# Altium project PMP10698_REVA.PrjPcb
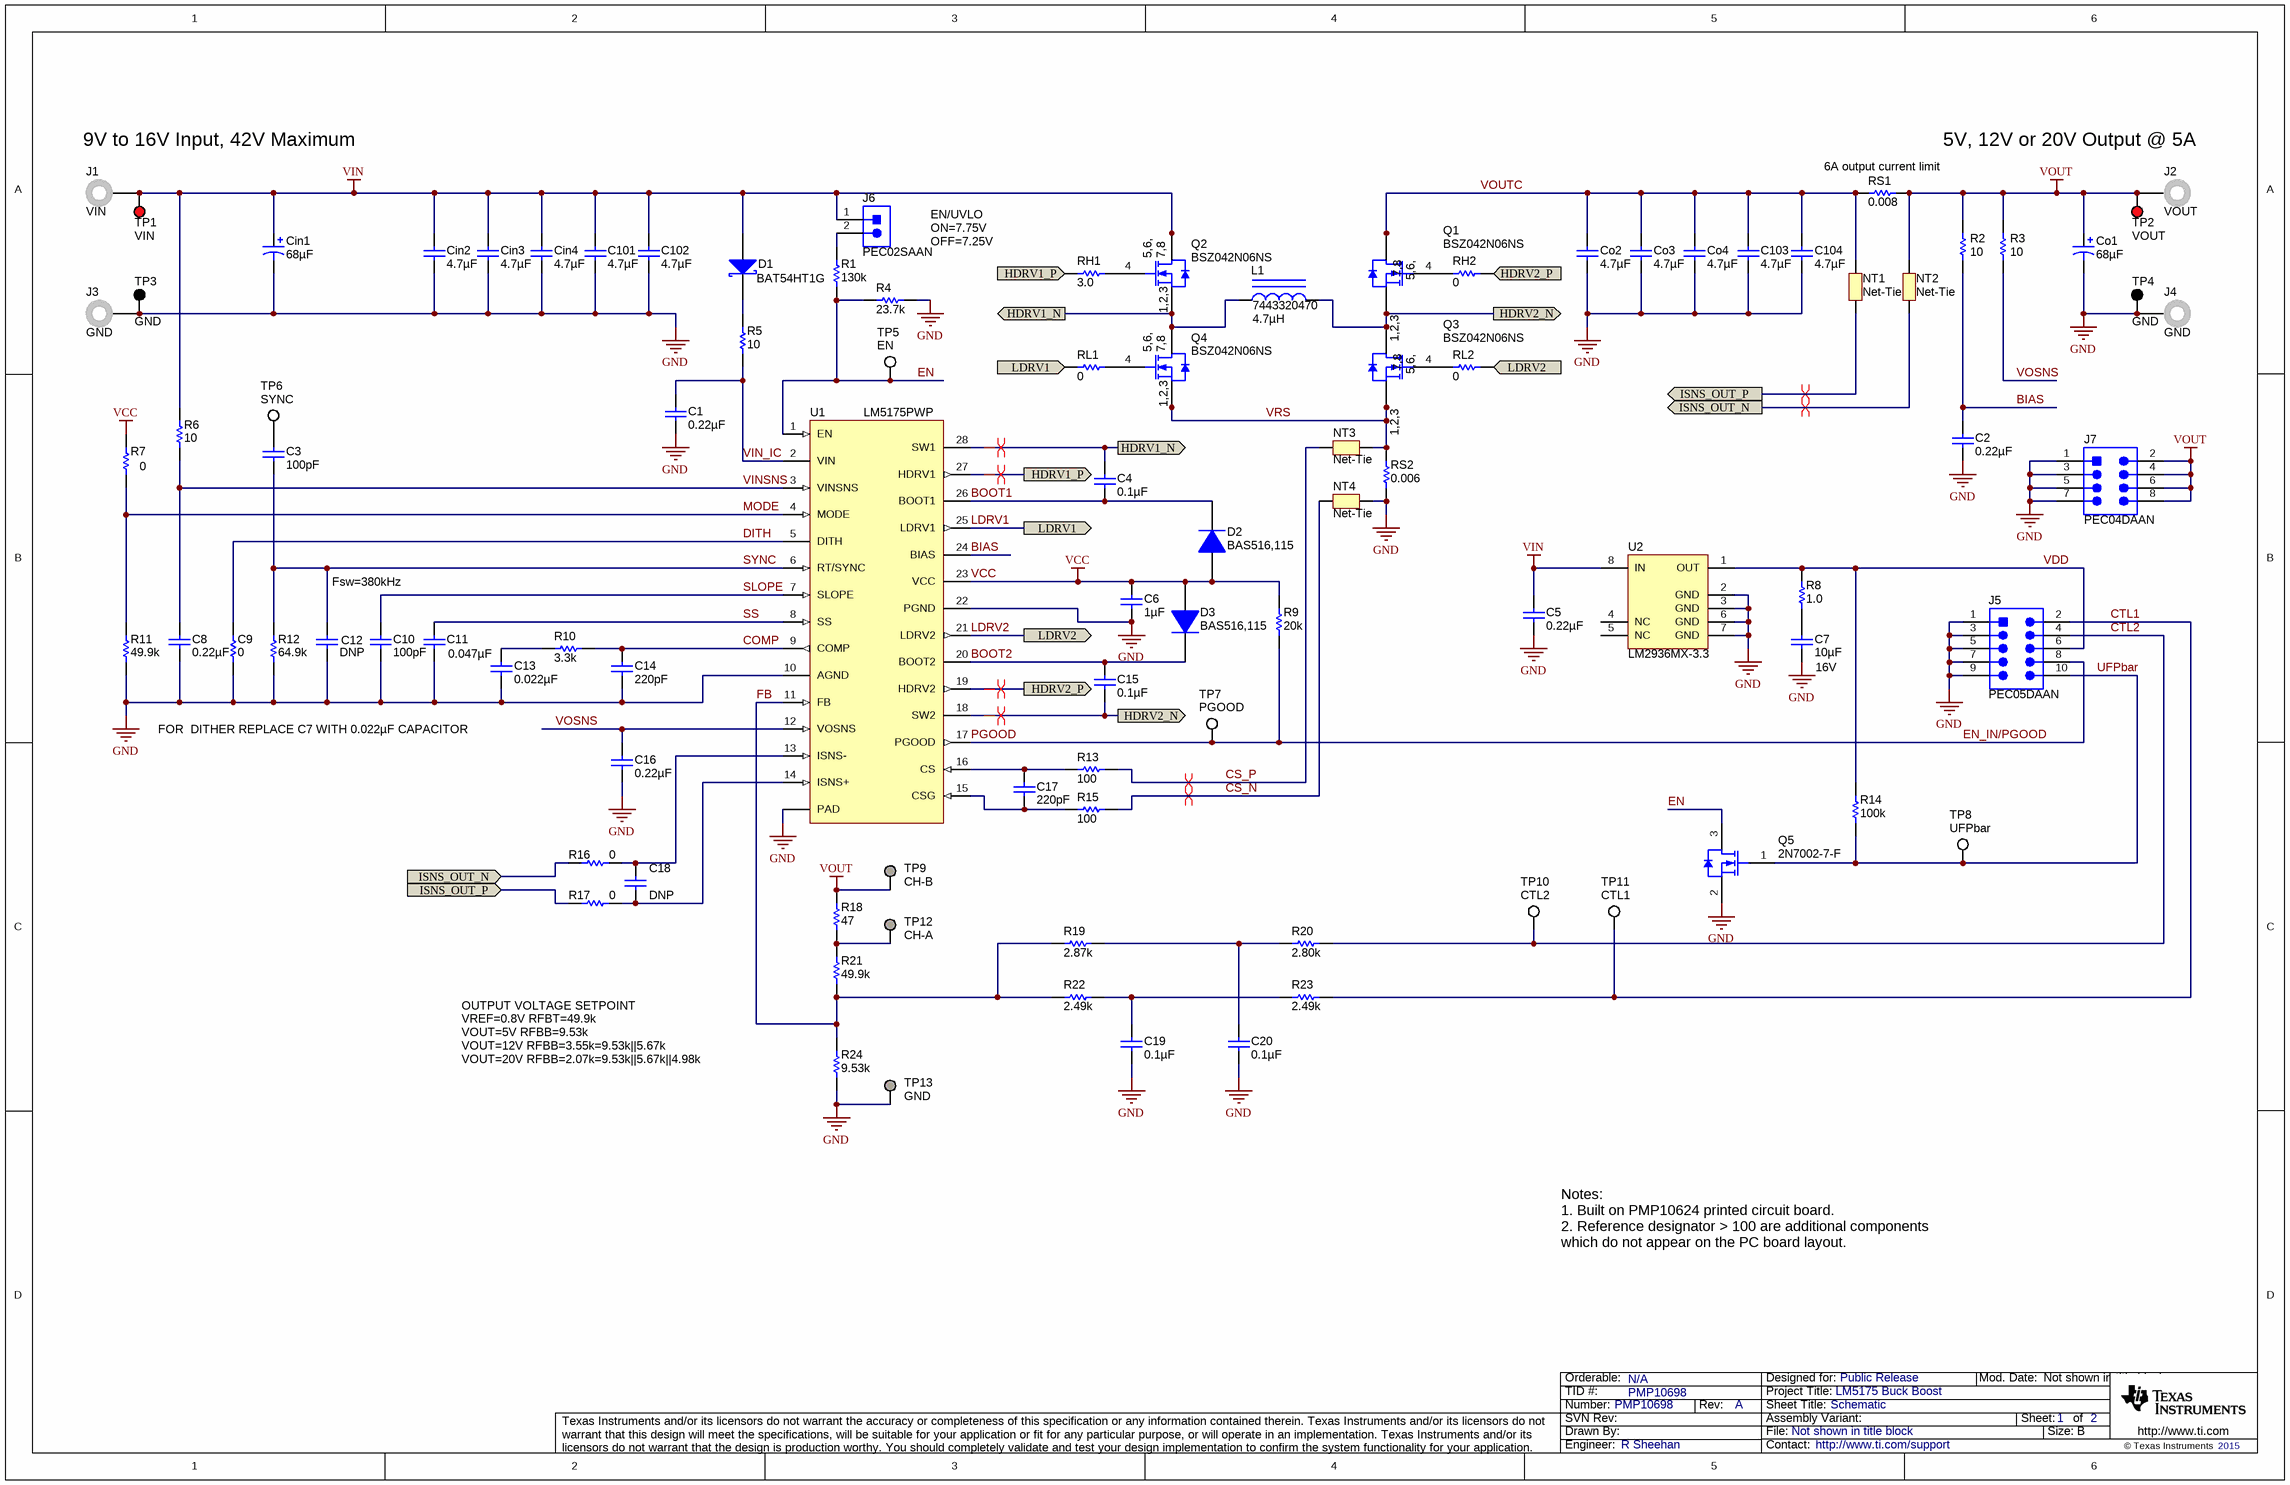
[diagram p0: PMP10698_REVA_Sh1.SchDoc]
CopyrightYear: 2015; EVM_Orderable: N/A; PCB_Rev: A; PRJ_Customer: Public Release; PRJ_Engineer: R Sheehan; PRJ_Number: PMP10698; PRJ_Title: LM5175 Buck Boost; SCH_Rev: A; TechSupport: http://www.ti.com/support; TID: PMP10698
2 sheets, 113 parts. Net scope: flat (ports and power ports of the same name join across sheets).
Board file: PMP10624_REVA.PcbDoc
Sheets:
  PMP10698_REVA_Sh1.SchDoc
  PMP10698_REVA_Sh2.SchDoc

## Sheet PMP10698_REVA_Sh1.SchDoc: Schematic
size 431 x 279 mm; Date: Not shown in title block; ApprovedBy: Not shown in title block; CheckedBy: Not shown in title block; Author: Not shown in title block; CompanyName: Not shown in title block; Engineer: Not shown in title block; Organization: Not shown in title block; Address1: Not shown in title block; Address2: Not shown in title block; Address3: Not shown in title block; Address4: Not shown in title block; DocumentNumber: 1; Revision: Use project parameter SCH_Rev; SheetNumber: 1; SheetTotal: 2; PageSetup: Record=PageOptions¦CenterHorizontal=True¦CenterVertical=True¦PrintScale=1.00¦XCorrection=1.00¦YCorrection=1.00¦PrintKind=0¦BorderSize=5000000¦LeftOffset=0¦BottomOffset=0¦Orientation=2¦PaperLength=1000¦PaperWidth=1000¦Scale=100¦PaperSource=15¦PrintQuality=600¦MediaType=1¦DitherType=10¦PaperKind=Letter¦PrintScaleMode=1

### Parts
C1  ValueDisplayed: 0.22µF  [0603L]  (hidden comment: C1608X7R1H224K080AB)
C2  ValueDisplayed: 0.22µF  [0603L]  (hidden comment: C1608X7R1H224K080AB)
C3  ValueDisplayed: 100pF  [0603L]  (hidden comment: GRM1885C1H101JA01D)
C4  ValueDisplayed: 0.1µF  [0603L]  (hidden comment: 06033C104JAT2A)
C5  ValueDisplayed: 0.22µF  [0603L]  (hidden comment: C1608X7R1H224K080AB)
C6  ValueDisplayed: 1µF  [0603L]  (hidden comment: GRM188R71C105KA12D)
C7  ValueDisplayed: 10µF  Value2: 16V  [0805_145]  (hidden comment: EMK212BB7106MG-T)
C8  ValueDisplayed: 0.22µF  [0603L]  (hidden comment: C1608X7R1H224K080AB)
C9  ValueDisplayed: 0  [0603L]  (hidden comment: CRCW06030000Z0EA)
C10  ValueDisplayed: 100pF  [0603L]  (hidden comment: GRM1885C1H101JA01D)
C11  ValueDisplayed: 0.047µF  [0603L]  (hidden comment: GRM188R71H473KA61D)
C12  DNP  [0603L]
C13  ValueDisplayed: 0.022µF  [0603L]  (hidden comment: GRM188R71H223KA01D)
C14  ValueDisplayed: 220pF  [0603L]  (hidden comment: GRM1885C1H221JA01D)
C15  ValueDisplayed: 0.1µF  [0603L]  (hidden comment: 06033C104JAT2A)
C16  ValueDisplayed: 0.22µF  [0603L]  (hidden comment: C1608X7R1H224K080AB)
C17  ValueDisplayed: 220pF  [0603L]  (hidden comment: GRM1885C1H221JA01D)
C18  DNP  [0603L]
C19  ValueDisplayed: 0.1µF  [0603L]  (hidden comment: 06033C104JAT2A)
C20  ValueDisplayed: 0.1µF  [0603L]  (hidden comment: 06033C104JAT2A)
C101  ValueDisplayed: 4.7µF  [1206L]  (hidden comment: GRM31CR71H475KA12L)
C102  ValueDisplayed: 4.7µF  [1206L]  (hidden comment: GRM31CR71H475KA12L)
C103  ValueDisplayed: 4.7µF  [1206L]  (hidden comment: GRM31CR71H475KA12L)
C104  ValueDisplayed: 4.7µF  [1206L]  (hidden comment: GRM31CR71H475KA12L)
Cin1  ValueDisplayed: 68µF  [SM_RADIAL_F]  (hidden comment: EEE-FK1J680UP)
Cin2  ValueDisplayed: 4.7µF  [1206L]  (hidden comment: GRM31CR71H475KA12L)
Cin3  ValueDisplayed: 4.7µF  [1206L]  (hidden comment: GRM31CR71H475KA12L)
Cin4  ValueDisplayed: 4.7µF  [1206L]  (hidden comment: GRM31CR71H475KA12L)
Co1  ValueDisplayed: 68µF  [SM_RADIAL_F]  (hidden comment: EEE-FK1J680UP)
Co2  ValueDisplayed: 4.7µF  [1206L]  (hidden comment: GRM31CR71H475KA12L)
Co3  ValueDisplayed: 4.7µF  [1206L]  (hidden comment: GRM31CR71H475KA12L)
Co4  ValueDisplayed: 4.7µF  [1206L]  (hidden comment: GRM31CR71H475KA12L)
D1  BAT54HT1G  [sod-323]
D2  BAS516,115  [SOD-523]
D3  BAS516,115  [SOD-523]
J1  VIN  [Keystone_575-4]
J2  VOUT  [Keystone_575-4]
J3  GND  [Keystone_575-4]
J4  GND  [Keystone_575-4]
J5  PEC05DAAN  [CONN_PEC05DAAN]
J6  PEC02SAAN  [CONN_PEC02SAAN]
J7  PEC04DAAN  [CONN_PEC04DAAN]
L1  7443320470  ValueDisplayed: 4.7µH  [WE-HCC_1210]
NT1  Net-Tie  [Net-Tie_10mil]  (net tie, no BOM)
NT2  Net-Tie  [Net-Tie_10mil]  (net tie, no BOM)
NT3  Net-Tie  [Net-Tie_10mil]  (net tie, no BOM)
NT4  Net-Tie  [Net-Tie_10mil]  (net tie, no BOM)
Q1  BSZ042N06NS  [PG-TSDSON-8]
Q2  BSZ042N06NS  [PG-TSDSON-8]
Q3  BSZ042N06NS  [PG-TSDSON-8]
Q4  BSZ042N06NS  [PG-TSDSON-8]
Q5  2N7002-7-F  [SOT-23]
R1  ValueDisplayed: 130k  [0603L]  (hidden comment: CRCW0603130KJNEA)
R2  value 10  [0603L]  (hidden comment: CRCW060310R0JNEA)
R3  ValueDisplayed: 10  [0603L]  (hidden comment: CRCW060310R0JNEA)
R4  ValueDisplayed: 23.7k  [0603L]  (hidden comment: CRCW060323K7FKEA)
R5  ValueDisplayed: 10  [0603L]  (hidden comment: CRCW060310R0JNEA)
R6  ValueDisplayed: 10  [0603L]  (hidden comment: CRCW060310R0JNEA)
R7  value 0  [0603L]  (hidden comment: CRCW06030000Z0EA)
R8  ValueDisplayed: 1.0  [0603L]  (hidden comment: CRCW06031R00JNEA)
R9  ValueDisplayed: 20k  [0603L]  (hidden comment: CRCW060320K0JNEA)
R10  ValueDisplayed: 3.3k  [0603L]  (hidden comment: CRCW06033K30JNEA)
R11  ValueDisplayed: 49.9k  [0603L]  (hidden comment: CRCW060349K9FKEA)
R12  ValueDisplayed: 64.9k  [0603L]  (hidden comment: CRCW060364K9FKEA)
R13  ValueDisplayed: 100  [0603L]  (hidden comment: CRCW0603100RFKEA)
R14  ValueDisplayed: 100k  [0603L]  (hidden comment: CRCW0603100KJNEA)
R15  ValueDisplayed: 100  [0603L]  (hidden comment: CRCW0603100RFKEA)
R16  value 0  [0603L]  (hidden comment: CRCW06030000Z0EA)
R17  value 0  [0603L]  (hidden comment: CRCW06030000Z0EA)
R18  ValueDisplayed: 47  [0603L]  (hidden comment: CRCW060347R0JNEA)
R19  ValueDisplayed: 2.87k  [0603L]  (hidden comment: CRCW06032K87FKEA)
R20  ValueDisplayed: 2.80k  [0603L]  (hidden comment: CRCW06032K80FKEA)
R21  ValueDisplayed: 49.9k  [0603L]  (hidden comment: CRCW060349K9FKEA)
R22  ValueDisplayed: 2.49k  [0603L]  (hidden comment: CRCW06032K49FKEA)
R23  ValueDisplayed: 2.49k  [0603L]  (hidden comment: CRCW06032K49FKEA)
R24  ValueDisplayed: 9.53k  [0603L]  (hidden comment: CRCW06039K53FKEA)
RH1  ValueDisplayed: 3.0  [0603L]  (hidden comment: CRCW06033R00JNEA)
RH2  value 0  [0603L]  (hidden comment: CRCW06030000Z0EA)
RL1  value 0  [0603L]  (hidden comment: CRCW06030000Z0EA)
RL2  value 0  [0603L]  (hidden comment: CRCW06030000Z0EA)
RS1  ValueDisplayed: 0.008  [2010]  (hidden comment: PMR50HZPFU8L00)
RS2  ValueDisplayed: 0.006  [2512]  (hidden comment: ERJ-M1WSF6M0U)
TP1  VIN  [Keystone5000]
TP2  VOUT  [Keystone5000]
TP3  GND  [Keystone5001]
TP4  GND  [Keystone5001]
TP5  EN  [Keystone5002]
TP6  SYNC  [Keystone5002]
TP7  PGOOD  [Keystone5002]
TP8  UFPbar  [Keystone5002]
TP9  CH-B  [Keystone1598-2]
TP10  CTL2  [Keystone5002]
TP11  CTL1  [Keystone5002]
TP12  CH-A  [Keystone1598-2]
TP13  GND  [Keystone1598-2]
U1  LM5175PWP  [PWP0028F_N]
U2  LM2936MX-3.3  [M08A_N]

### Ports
HDRV1_N, HDRV1_P (out), HDRV2_N, HDRV2_P (out), ISNS_OUT_N (in), ISNS_OUT_N (out), ISNS_OUT_P (in), ISNS_OUT_P (out), LDRV1 (out), LDRV2 (out)

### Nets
GND: C1.2 C2.2 C5.2 C6.2 C7.2 C8.1 C9.1 C10.2 C11.2 C12.1 C13.2 C14.2 C16.2 C19.2 C20.2 C101.2 C102.2 C103.2 C104.2 Cin1.2(-) Cin2.2 Cin3.2 Cin4.2 Co1.2(-) Co2.2 Co3.2 Co4.2 J3.1 J4.1 J5.1 J5.3 J5.5 J5.7 J5.9 J7.1 J7.3 J7.5 J7.7 NT4.1 Q5.2(S) R4.1 R11.1 R12.1 R24.1 RS2.1 TP3.1 TP4.1 TP13.1 U1.10(AGND) U1.22(PGND) U1.29(PAD) U2.2(GND) U2.3(GND) U2.6(GND) U2.7(GND)
VCC: C6.1 D2.2(A) D3.2(A) R7.2 R9.2 U1.23(VCC)
VIN: C5.1 C101.1 C102.1 Cin1.1(+) Cin2.1 Cin3.1 Cin4.1 D1.2(A) J1.1 J6.1 Q2.5(D) Q2.6(D) Q2.7(D) Q2.8(D) Q2.9(D) R6.1 TP1.1 U2.8(IN)
VOUT: Co1.1(+) J2.1 J7.2 J7.4 J7.6 J7.8 NT2.2 R2.2 R3.2 R18.1 RS1.2 TP2.1 TP9.1
BIAS: C2.1 R2.1 U1.24(BIAS)
BOOT1: C4.1 D2.1(K) U1.26(BOOT1)
BOOT2: C15.2 D3.1(K) U1.20(BOOT2)
COMP: C14.1 R10.2 U1.9(COMP)
CS_N: NT4.2 R15.2
CS_P: NT3.2 R13.2
CTL1: J5.2 R23.1 TP11.1
CTL2: J5.4 R20.1 TP10.1
DITH: C9.2 U1.5(DITH)
EN: Q5.3(D) R1.1 R4.2 TP5.1 U1.1(EN)
EN_IN/PGOOD: J5.8 R9.1 TP7.1 U1.17(PGOOD)  [also labelled PGOOD]
FB: R19.2 R21.1 R22.2 R24.2 U1.11(FB)
HDRV1_N: C4.2 L1.1 Q2.1(S) Q2.2(S) Q2.3(S) Q4.5(D) Q4.6(D) Q4.7(D) Q4.8(D) Q4.9(D) U1.28(SW1) ; port HDRV1_N
HDRV1_P: RH1.1 U1.27(HDRV1) ; port HDRV1_P
HDRV2_N: C15.1 L1.2 Q1.1(S) Q1.2(S) Q1.3(S) Q3.5(D) Q3.6(D) Q3.7(D) Q3.8(D) Q3.9(D) U1.18(SW2) ; port HDRV2_N
HDRV2_P: RH2.2 U1.19(HDRV2) ; port HDRV2_P
ISNS_OUT_N: NT2.1 R16.1 ; port ISNS_OUT_N
ISNS_OUT_P: NT1.1 R17.1 ; port ISNS_OUT_P
LDRV1: RL1.1 U1.25(LDRV1) ; port LDRV1
LDRV2: RL2.2 U1.21(LDRV2) ; port LDRV2
MODE: R7.1 R11.2 U1.4(MODE)
SLOPE: C10.1 U1.7(SLOPE)
SS: C11.1 U1.8(SS)
SYNC: C3.2 C12.2 R12.2 U1.6(RT/SYNC)
UFPbar: J5.10 Q5.1(G) R14.1 TP8.1
VDD: J5.6 R8.2 R14.2 U2.1(OUT)
VIN_IC: C1.1 R5.1 U1.2(VIN)
VINSNS: C8.2 R6.2 U1.3(VINSNS)
VOSNS: C16.1 R3.1 U1.12(VOSNS)
VOUTC: C103.1 C104.1 Co2.1 Co3.1 Co4.1 NT1.2 Q1.5(D) Q1.6(D) Q1.7(D) Q1.8(D) Q1.9(D) RS1.1
VRS: NT3.1 Q3.1(S) Q3.2(S) Q3.3(S) Q4.1(S) Q4.2(S) Q4.3(S) RS2.2
NetC3_1: C3.1 TP6.1
NetC7_1: C7.1 R8.1
NetC13_1: C13.1 R10.1
NetC17_1: C17.1 R13.1 U1.16(CS)
NetC17_2: C17.2 R15.1 U1.15(CSG)
NetC18_1: C18.1 R16.2 U1.13(ISNS-)
NetC18_2: C18.2 R17.2 U1.14(ISNS+)
NetC19_1: C19.1 R22.1 R23.2
NetC20_1: C20.1 R19.1 R20.2
NetD1_1: D1.1(K) R5.2
NetJ6_2: J6.2 R1.2
NetQ1_4: Q1.4(G) RH2.1
NetQ2_4: Q2.4(G) RH1.2
NetQ3_4: Q3.4(G) RL2.1
NetQ4_4: Q4.4(G) RL1.2
NetR18_2: R18.2 R21.2 TP12.1

Not connected (* = marked no-connect by the designer): U2 4(NC) 5(NC)

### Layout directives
differential pair: CS_N, CS_P, HDRV1_N, HDRV1_P, HDRV2_N, HDRV2_P, ISNS_OUT_N, ISNS_OUT_P

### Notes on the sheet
- 9V to 16V Input, 42V Maximum
- (near RS1) 6A output current limit
- 5V, 12V or 20V Output @ 5A
- EN/UVLO
  ON=7.75V
  OFF=7.25V
- Fsw=380kHz
- FOR  DITHER REPLACE C7 WITH 0.022µF CAPACITOR
- OUTPUT VOLTAGE SETPOINT
  VREF=0.8V RFBT=49.9k
  VOUT=5V RFBB=9.53k
  VOUT=12V RFBB=3.55k=9.53k||5.67k
  VOUT=20V RFBB=2.07k=9.53k||5.67k||4.98k
- Notes:
  1. Built on PMP10624 printed circuit board.
  2. Reference designator > 100 are additional components which do not appear on the PC board layout.

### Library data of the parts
C1 C2 C5 = C1608X7R1H224K080AB: CAP, CERM, 0.22uF, 50V, +/-10%, X7R, 0603; Manufacturer: TDK; Polarized: N; CompType: Capacitor; U/M: EA; Cap_F: 0.00000022; Tolerance_%: 10; Value1: Unknown; VDC_V: 50; TaMin_C: -55; TaMax_C: 125; Cap_Case: 0603
C3 C10 = GRM1885C1H101JA01D: CAP, CERM, 100 pF, 50 V, +/- 5%, C0G/NP0, 0603; Manufacturer: MuRata; Polarized: N; CompType: Capacitor; Value: 100pF; U/M: EA; Cap_F: 0.0000000001; Tolerance_%: 5; Value1: Unknown; VDC_V: 50; Value2: 50V; TaMin_C: -55; TaMax_C: 125; Cap_Case: 0603
C4 C15 C19 C20 = 06033C104JAT2A: CAP, CERM, 0.1 µF, 25 V, +/- 5%, X7R, 0603; Manufacturer: AVX; Polarized: N; CompType: Capacitor; Value: 0.1uF; U/M: EA; Cap_F: 0.0000001; Tolerance_%: 5; ESR_ohm: 0.05; Value1: 0.05 ohm; VDC_V: 25; Value2: 25V; TaMin_C: -55; TaMax_C: 125; Cap_Case: 0603
C6 = GRM188R71C105KA12D: CAP, CERM, 1uF, 16V, +/-10%, X7R, 0603; Manufacturer: MuRata; Polarized: N; CompType: Capacitor; U/M: EA; Cap_F: 0.000001; Tolerance_%: 10; ESR_Ohm: 0.011; Value1: 0.011 ohm; VDC_V: 16; TaMin_C: -55; TaMax_C: 125; Cap_Case: 0603
C7 = EMK212BB7106MG-T: CAP, CERM, 10 µF, 16 V, +/- 20%, X7R, 0805; Manufacturer: Taiyo Yuden; Polarized: N; CompType: Capacitor; Value: 10uF; U/M: EA; Cap_F: 0.00001; Tolerance_%: 20; Value1: Unknown; VDC_V: 16; TaMin_C: -55; TaMax_C: 125; Cap_Case: 0805
C8 C16 = C1608X7R1H224K080AB: CAP, CERM, 0.22 µF, 50 V, +/- 10%, X7R, 0603; Manufacturer: TDK; Polarized: N; CompType: Capacitor; Value: 0.22uF; U/M: EA; Cap_F: 0.00000022; Tolerance_%: 10; Value1: Unknown; VDC_V: 50; Value2: 50V; TaMin_C: -55; TaMax_C: 125; Cap_Case: 0603
C9 = CRCW06030000Z0EA: RES, 0, 5%, 0.1 W, 0603; Manufacturer: Vishay-Dale; CompType: Resistor; Value: 0; Tolerance_%: 5; Value2: 0.1W; VDC_V: 75; TempCo: 200 ppm/C; U/M: EA; Value_Code: 0000; Power_W: 0.1; EIA_Code: E24
C11 = GRM188R71H473KA61D: CAP, CERM, 0.047 µF, 50 V, +/- 10%, X7R, 0603; Manufacturer: MuRata; Polarized: N; CompType: Capacitor; Value: 0.047uF; U/M: EA; Cap_F: 0.000000047; Tolerance_%: 10; Value1: Unknown; VDC_V: 50; Value2: 50V; TaMin_C: -55; TaMax_C: 125; Cap_Case: 0603
C12 C18 = GRM1885C1H101JA01D: CAP, CERM, 100pF, 50V, +/-5%, C0G/NP0, 0603; Manufacturer: MuRata; Polarized: N; CompType: Capacitor; U/M: EA; Cap_F: 0.0000000001; Tolerance_%: 5; Value1: Unknown; VDC_V: 50; TaMin_C: -55; TaMax_C: 125; Cap_Case: 0603
C13 = GRM188R71H223KA01D: CAP, CERM, 0.022 µF, 50 V, +/- 10%, X7R, 0603; Manufacturer: MuRata; Polarized: N; CompType: Capacitor; Value: 0.022uF; U/M: EA; Cap_F: 0.000000022; Tolerance_%: 10; Value1: Unknown; VDC_V: 50; Value2: 50V; TaMin_C: -55; TaMax_C: 125; Cap_Case: 0603
C14 C17 = GRM1885C1H221JA01D: CAP, CERM, 220 pF, 50 V, +/- 5%, C0G/NP0, 0603; Manufacturer: MuRata; Polarized: N; CompType: Capacitor; Value: 220pF; U/M: EA; Cap_F: 0.00000000022; Tolerance_%: 5; Value1: Unknown; VDC_V: 50; Value2: 50V; TaMin_C: -55; TaMax_C: 125; Cap_Case: 0603
C101-C104 Cin2-Cin4 Co2-Co4 = GRM31CR71H475KA12L: CAP, CERM, 4.7 µF, 50 V, +/- 10%, X7R, 1206; Manufacturer: MuRata; Polarized: N; CompType: Capacitor; Value: 4.7uF; U/M: EA; Cap_F: 0.0000047; Tolerance_%: 10; Value1: Unknown; VDC_V: 50; Value2: 50V; TaMin_C: -55; TaMax_C: 125; Cap_Case: 2220
Cin1 Co1 = EEE-FK1J680UP: CAP, AL, 68 µF, 63 V, +/- 20%, 0.65 ohm, SMD; Manufacturer: Panasonic; Polarized: Y; CompType: Capacitor; Value: 68uF; U/M: EA; Cap_F: 0.000068; Tolerance_%: 20; VDC_V: 63; Value2: 63V; ESR_ohm: 0.65; IRMS_A: 0.25; TaMin_C: -55; TaMax_C: 105; Cap_Case: F
D1 = BAT54HT1G: Diode, Schottky, 30V, 0.2A, SOD-323; Manufacturer: ON Semiconductor; U/M: EA; Vf_V: 0.35; Value2: 0.35V; Io_A: 0.2; Vr_V: 30
D2 D3 = BAS516,115: Diode, Switching, 100V, 0.25A, SOD-523; Manufacturer: NXP Semiconductor; U/M: EA; Vf_V: 1.25; Value2: 1.25V; Io_A: 0.25; Vr_V: 100; TJmax_C: 150
J1-J4 = 575-4: Standard Banana Jack, Uninsulated, 5.5mm; Manufacturer: Keystone; CompType: Connector; U/M: EA
J5 = PEC05DAAN: Header, 100mil, 5x2, Tin, TH; Manufacturer: Sullins Connector Solutions; SymbolCreator: a0412235; U/M: EA
J6 = PEC02SAAN: Header, 100mil, 2x1, Tin, TH; Manufacturer: Sullins Connector Solutions; SymbolCreator: a0412235; U/M: EA
J7 = PEC04DAAN: Header, 100mil, 4x2, Tin, TH; Manufacturer: Sullins Connector Solutions; SymbolCreator: a0411947; U/M: EA
L1 = 7443320470: Inductor, Shielded Drum Core, Ferrite, 4.7 µH, 15.5 A, 0.0064 ohm, SMD; Manufacturer: Wurth Elektronik; Value: 4.7uH; Ind_H: 4.7E-6; Imax_A: 15.5; Irms: 15.5A @ 50C rise; Isat: 17A @ 30% inductance drop; DCR_ohm: 0.0064; Value2: 15.5A
NT1-NT4 = Net-Tie: Single point connection between nets.; SymbolCreator: codlsc
Q1-Q4 = BSZ042N06NS: MOSFET, N-CH, 60 V, 17 A, PG-TSDSON-8; Manufacturer: Infineon Technologies; Alternate Manufacturer: None; U/M: EA; ChType: N; Value: 60V; VdsMax_V: 60; Value1: ? ohm; Value2: 27 nC; QgTyp_nC: 27; Vgs_V: 20; IdsMax_A: 17
Q5 = 2N7002-7-F: MOSFET, N-CH, 60 V, 0.17 A, SOT-23; Manufacturer: Diodes Inc.; Alternate Manufacturer: None; U/M: EA; ChType: N; Value: 60V; VdsMax_V: 60; Value1: 7.5 ohm; Rdson45_ohm: 7.5; Value2: 223 nC; QgTyp_nC: 223; Vgs_V: 20; IdsMax_A: 0.17
R1 = CRCW0603130KJNEA: RES, 130 k, 5%, 0.1 W, 0603; Manufacturer: Vishay-Dale; CompType: Resistor; Value: 130k; Res_ohm: 130000; Tolerance_%: 5; Power_W: 0.1; Value2: 0.1W; VDC_V: 75; TempCo: 200 ppm/C; EIA_Code: E24; U/M: EA
R2 = CRCW060310R0JNEA: RES, 10, 5%, 0.1 W, 0603; Manufacturer: Vishay-Dale; CompType: Resistor; Value_Code: 10R0; Tolerance_%: 5; Power_W: 0.1; Value2: 0.1W; VDC_V: 75; TempCo: 200 ppm/C; EIA_Code: E24; U/M: EA
R3 = CRCW060310R0JNEA: RES, 10, 5%, 0.1 W, 0603; Manufacturer: Vishay-Dale; CompType: Resistor; Value_Code: 10R0; Tolerance_%: 5; Power_W: 0.1; Value2: 0.1W; VDC_V: 75; TempCo: 200 ppm/C; EIA_Code: E24; U/M: EA; Value: 10
R4 = CRCW060323K7FKEA: RES, 23.7 k, 1%, 0.1 W, 0603; Manufacturer: Vishay-Dale; CompType: Resistor; Value: 23.7k; Res_ohm: 23700; Value_Code: 23k7; Tolerance_%: 1; Power_W: 0.1; Value2: 0.1W; VDC_V: 75; TempCo: 100 ppm/C; EIA_Code: E96; U/M: EA
R5 R6 = CRCW060310R0JNEA: RES, 10, 5%, 0.1 W, 0603; Manufacturer: Vishay-Dale; CompType: Resistor; Value: 10; Value_Code: 10R0; Tolerance_%: 5; Power_W: 0.1; Value2: 0.1W; VDC_V: 75; TempCo: 200 ppm/C; EIA_Code: E24; U/M: EA
R7 = CRCW06030000Z0EA: RES, 0, 5%, 0.1 W, 0603; Manufacturer: Vishay-Dale; CompType: Resistor; Value_Code: 0000; Tolerance_%: 5; Power_W: 0.1; Value2: 0.1W; VDC_V: 75; TempCo: 200 ppm/C; EIA_Code: E24; U/M: EA
R8 = CRCW06031R00JNEA: RES, 1.0, 5%, 0.1 W, 0603; Manufacturer: Vishay-Dale; CompType: Resistor; Value: 1.0; Res_ohm: 1; Value_Code: 1R00; Tolerance_%: 5; Power_W: 0.1; Value2: 0.1W; VDC_V: 75; TempCo: 200 ppm/C; EIA_Code: E24; U/M: EA
R9 = CRCW060320K0JNEA: RES, 20 k, 5%, 0.1 W, 0603; Manufacturer: Vishay-Dale; CompType: Resistor; Value: 20k; Res_ohm: 20000; Value_Code: 20k0; Tolerance_%: 5; Power_W: 0.1; Value2: 0.1W; VDC_V: 75; TempCo: 200 ppm/C; EIA_Code: E24; U/M: EA
R10 = CRCW06033K30JNEA: RES, 3.3 k, 5%, 0.1 W, 0603; Manufacturer: Vishay-Dale; CompType: Resistor; Res_ohm: 3300; Value_Code: 3k30; Tolerance_%: 5; Power_W: 0.1; Value2: 0.1W; VDC_V: 75; TempCo: 200 ppm/C; EIA_Code: E24; U/M: EA; Value: 3.3k
R11 R21 = CRCW060349K9FKEA: RES, 49.9 k, 1%, 0.1 W, 0603; Manufacturer: Vishay-Dale; CompType: Resistor; Value: 49.9k; Res_ohm: 49900; Value_Code: 49k9; Tolerance_%: 1; Power_W: 0.1; Value2: 0.1W; VDC_V: 75; TempCo: 100 ppm/C; EIA_Code: E96; U/M: EA
R12 = CRCW060364K9FKEA: RES, 64.9 k, 1%, 0.1 W, 0603; Manufacturer: Vishay-Dale; CompType: Resistor; Value: 64.9k; Res_ohm: 64900; Value_Code: 64k9; Tolerance_%: 1; Power_W: 0.1; Value2: 0.1W; VDC_V: 75; TempCo: 100 ppm/C; EIA_Code: E96; U/M: EA
R13 R15 = CRCW0603100RFKEA: RES, 100, 1%, 0.1 W, 0603; Manufacturer: Vishay-Dale; CompType: Resistor; Value: 100; Value_Code: 100R; Tolerance_%: 1; Power_W: 0.1; Value2: 0.1W; VDC_V: 75; TempCo: 100 ppm/C; EIA_Code: E96; U/M: EA
R14 = CRCW0603100KJNEA: RES, 100 k, 5%, 0.1 W, 0603; Manufacturer: Vishay-Dale; CompType: Resistor; Value: 100k; Res_ohm: 100000; Tolerance_%: 5; Power_W: 0.1; Value2: 0.1W; VDC_V: 75; TempCo: 200 ppm/C; EIA_Code: E24; U/M: EA
R16 R17 RH2 RL1 RL2 = CRCW06030000Z0EA: RES, 0 ohm, 5%, 0.1W, 0603; Manufacturer: Vishay-Dale; CompType: Resistor; Value_Code: 0000; Tolerance_%: 5; Power_W: 0.1; VDC_V: 75; TempCo: 200 ppm/C; EIA_Code: E24; U/M: EA
R18 = CRCW060347R0JNEA: RES, 47, 5%, 0.1 W, 0603; Manufacturer: Vishay-Dale; CompType: Resistor; Value: 47; Value_Code: 47R0; Tolerance_%: 5; Power_W: 0.1; Value2: 0.1W; VDC_V: 75; TempCo: 200 ppm/C; EIA_Code: E24; U/M: EA
R19 = CRCW06032K87FKEA: RES, 2.87 k, 1%, 0.1 W, 0603; Manufacturer: Vishay-Dale; CompType: Resistor; Value: 2.87k; Res_ohm: 2870; Value_Code: 2k87; Tolerance_%: 1; Power_W: 0.1; Value2: 0.1W; VDC_V: 75; TempCo: 100 ppm/C; EIA_Code: E96; U/M: EA
R20 = CRCW06032K80FKEA: RES, 2.80 k, 1%, 0.1 W, 0603; Manufacturer: Vishay-Dale; CompType: Resistor; Value: 2.80k; Res_ohm: 2800; Value_Code: 2k80; Tolerance_%: 1; Power_W: 0.1; Value2: 0.1W; VDC_V: 75; TempCo: 100 ppm/C; EIA_Code: E96; U/M: EA
R22 R23 = CRCW06032K49FKEA: RES, 2.49 k, 1%, 0.1 W, 0603; Manufacturer: Vishay-Dale; CompType: Resistor; Value: 2.49k; Res_ohm: 2490; Value_Code: 2k49; Tolerance_%: 1; Power_W: 0.1; Value2: 0.1W; VDC_V: 75; TempCo: 100 ppm/C; EIA_Code: E96; U/M: EA
R24 = CRCW06039K53FKEA: RES, 9.53 k, 1%, 0.1 W, 0603; Manufacturer: Vishay-Dale; CompType: Resistor; Value: 9.53k; Res_ohm: 9530; Value_Code: 9k53; Tolerance_%: 1; Power_W: 0.1; Value2: 0.1W; VDC_V: 75; TempCo: 100 ppm/C; EIA_Code: E96; U/M: EA
RH1 = CRCW06033R00JNEA: RES, 3.0, 5%, 0.1 W, 0603; Manufacturer: Vishay-Dale; CompType: Resistor; Value: 3.0; Res_ohm: 3; Value_Code: 3R00; Tolerance_%: 5; Power_W: 0.1; Value2: 0.1W; VDC_V: 75; TempCo: 200 ppm/C; EIA_Code: E24; U/M: EA
RS1 = PMR50HZPFU8L00: RES, 0.008, 1%, 1 W, 2010; Manufacturer: Rohm; CompType: Resistor; Value: 0.008; Tolerance_%: 1; TempCo: 100 ppm/C; U/M: EA; Value_Code: 8L000; Value2: 1W; EIA_Code: E96
RS2 = ERJ-M1WSF6M0U: RES, 0.006, 1%, 1 W, 2512; Manufacturer: Panasonic; CompType: Resistor; Value: 0.006; Tolerance_%: 1; TempCo: 100 ppm/C; U/M: EA; Value_Code: 6L000; Value2: 1W; EIA_Code: E96
TP1 TP2 = 5000: Test Point, TH, Miniature, Red; Manufacturer: Keystone; CompType: Test Point Loop; U/M: EA
TP3 TP4 = 5001: Test Point, TH, Miniature, Black; Manufacturer: Keystone; CompType: Test Point Loop; U/M: EA
TP5-TP8 TP10 TP11 = 5002: Test Point, Miniature, White, TH; Manufacturer: Keystone; CompType: Test Point Loop; U/M: EA
TP9 TP12 TP13 = 1598-2: Terminal, Turret, TH, Triple; Manufacturer: Keystone; CompType: Turret Terminal; U/M: EA
U1 = LM5175PWP: 42V Wide VIN 4-Switch Synchronous Buck-Boost Controller, PWP0028F; Alternate Manufacturer: None; Manufacturer: Texas Instruments; SymbolCreator: a0411947; CompType: IC; U/M: EA
U2 = LM2936MX-3.3: Ultra-Low Quiescent Current LDO Voltage Regulator, 8-pin Narrow SOIC; Manufacturer: Texas Instruments; PackageTopMarking: NSZXTT*LM293*6-3.3; PowerWise: N; CompType: LDO IC

## Sheet PMP10698_REVA_Sh2.SchDoc: Hardware
size 431 x 279 mm; Date: Not shown in title block; ApprovedBy: Not shown in title block; CheckedBy: Not shown in title block; Author: Not shown in title block; CompanyName: Not shown in title block; Engineer: Not shown in title block; Organization: Not shown in title block; Address1: Not shown in title block; Address2: Not shown in title block; Address3: Not shown in title block; Address4: Not shown in title block; DocumentNumber: 2; Revision: Use project parameter SCH_Rev; SheetNumber: 2; SheetTotal: 2; PageSetup: Record=PageOptions¦CenterHorizontal=True¦CenterVertical=True¦PrintScale=1.00¦XCorrection=1.00¦YCorrection=1.00¦PrintKind=0¦BorderSize=5000000¦LeftOffset=0¦BottomOffset=0¦Orientation=2¦PaperLength=1000¦PaperWidth=1000¦Scale=100¦PaperSource=15¦PrintQuality=600¦MediaType=1¦DitherType=10¦PaperKind=Letter¦PrintScaleMode=1
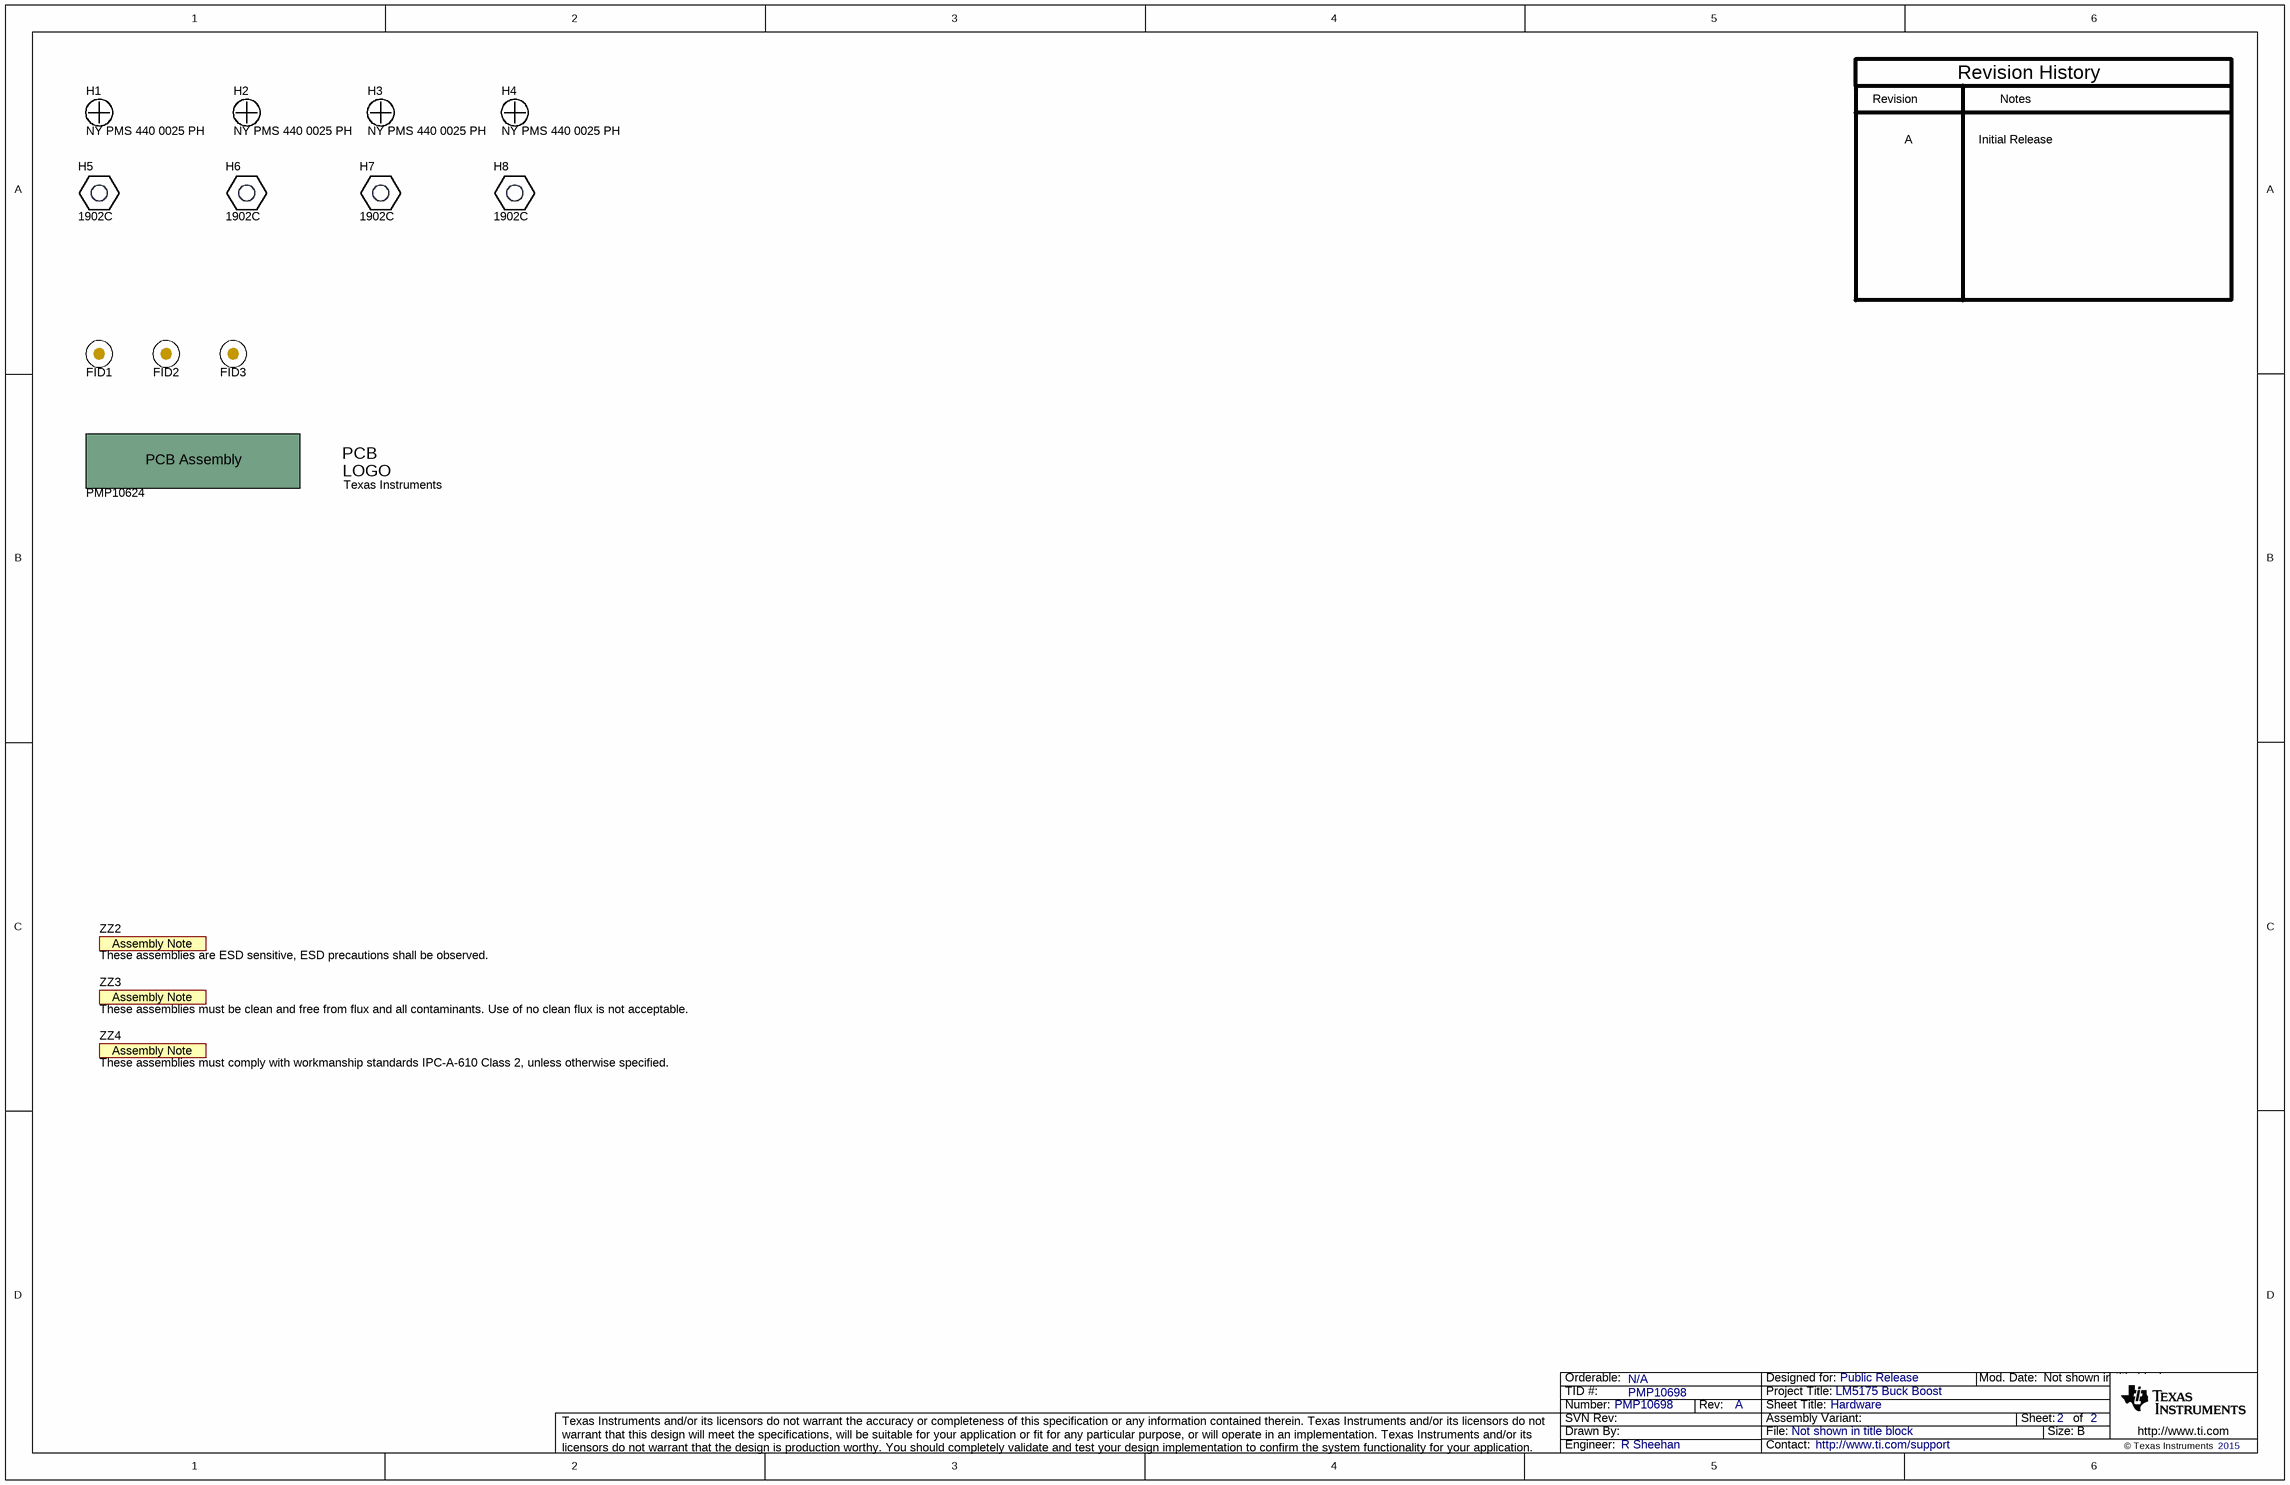
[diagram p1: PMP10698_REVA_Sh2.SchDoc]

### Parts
!PCBA  PMP10624  (mechanical)
FID1  Fiducial  [Fiducial10-20]  (value not drawn)
FID2  Fiducial  [Fiducial10-20]  (value not drawn)
FID3  Fiducial  [Fiducial10-20]  (value not drawn)
H1  NY PMS 440 0025 PH  [NY PMS 440 0025 PH]
H2  NY PMS 440 0025 PH  [NY PMS 440 0025 PH]
H3  NY PMS 440 0025 PH  [NY PMS 440 0025 PH]
H4  NY PMS 440 0025 PH  [NY PMS 440 0025 PH]
H5  1902C  [Keystone_1902C]
H6  1902C  [Keystone_1902C]
H7  1902C  [Keystone_1902C]
H8  1902C  [Keystone_1902C]
Logo1  Texas Instruments  [TI_Stacked_SolderMask_Small]  (no BOM)
ZZ2  These assemblies are ESD sensitive, ESD precautions shall be observed.  [AssemblyNote]  (no BOM)
ZZ3  These assemblies must be clean and free from flux and all contaminants. Use of no clean flux is not acceptable.  [AssemblyNote]  (no BOM)
ZZ4  These assemblies must comply with workmanship standards IPC-A-610 Class 2, unless otherwise specified.  [AssemblyNote]  (no BOM)

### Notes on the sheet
- Revision
- Notes
- Revision History
- A
- Initial Release

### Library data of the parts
!PCBA = PCBA: Manufacturer: Any; SymbolCreator: a0412235; U/M: EA
FID1-FID3 = Fiducial: Fiducial mark.  There is nothing to buy or mount.; SymbolCreator: codlsc
H1-H4 = NY PMS 440 0025 PH: Machine Screw, Round, #4-40 x 1/4, Nylon, Philips panhead; Manufacturer: B&F Fastener Supply; CompType: Hardware; SymbolCreator: codlsc; U/M: EA
H5-H8 = 1902C: Standoff, Hex, 0.5"L #4-40 Nylon; Manufacturer: Keystone; CompType: Hardware
Logo1 = TI_Logo: Texas Instrument Corporate Signature; SymbolCreator: codlsc
ZZ2-ZZ4 = AssemblyNote: SymbolCreator: codlsc

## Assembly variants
001: not fitted C12 C18 FID1 FID2 FID3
